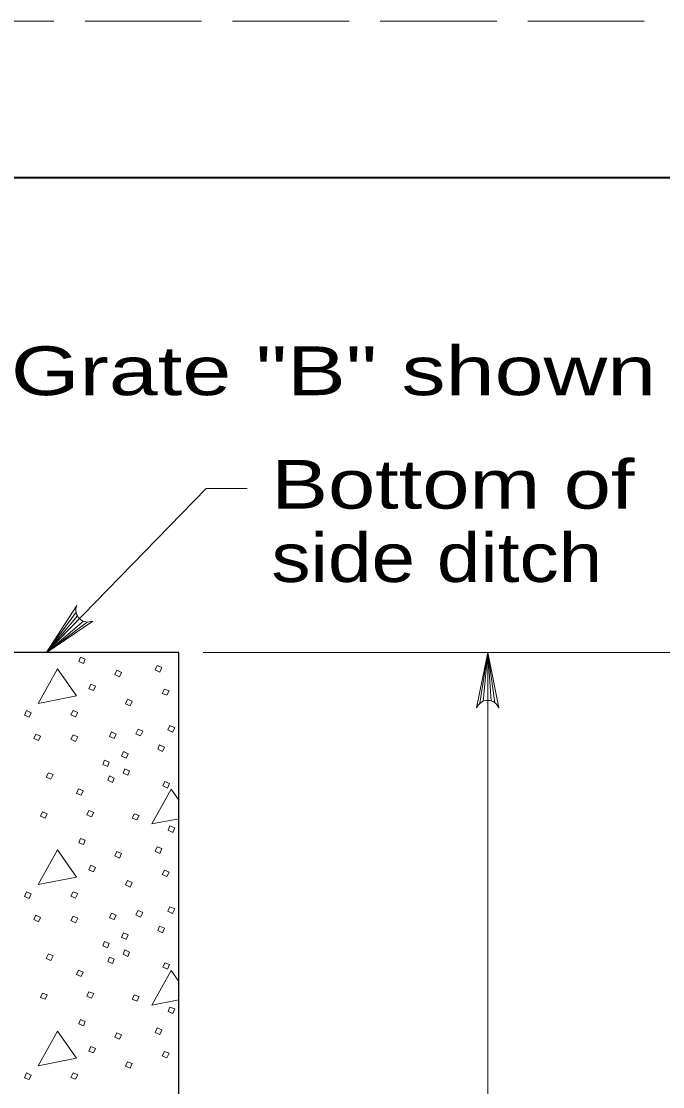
# Model space of a CAD drawing. Extents: x 1036.7 to 1070.7, y 883.9 to 905.9.
# Drawn here: x 1043.194 to 1045.244, y 902.5 to 905.908 of the extents above; entities that cross this region are included whole.
import ezdxf

# ---------------------------------------------------------------- set-up
doc = ezdxf.new("R2010")
doc.units = 0
doc.header["$LTSCALE"] = 0.062
doc.linetypes.add('LONG_DASHED', pattern=[7.5, 6, -1.5])
doc.layers.add('1', color=7, linetype='Continuous', lineweight=13)

msp = doc.modelspace()

# ---------------------------------------------------------------- linework, layer by layer
at = {"layer": '1', "lineweight": 25}
for p, q in [((1038.67333, 905.40825), (1070.17333, 905.40825)), ((1043.69742, 903.88892), (1043.04492, 903.88892)), ((1043.69742, 900.57758), (1043.69742, 903.88892))]:
    msp.add_line(p, q, dxfattribs=at)
at = {"layer": '1'}
for p, q in [((1043.27283, 903.88783), (1043.78483, 904.41408)), ((1043.91542, 904.41408), (1043.78483, 904.41408)), ((1043.36875, 904.01817), (1043.27283, 903.88783)), ((1043.37283, 904.0065), (1043.27283, 903.88783)), ((1043.37983, 903.99742), (1043.27283, 903.88783)), ((1043.39208, 903.98942), (1043.27283, 903.88783)), ((1043.40383, 903.98658), (1043.27283, 903.88783)), ((1043.7755, 903.88892), (1045.66242, 903.88892)), ((1044.65992, 903.72675), (1044.68467, 903.88892)), ((1044.67025, 903.73292), (1044.68467, 903.88892)), ((1044.68467, 900.40125), (1044.68467, 903.88892)), ((1044.68467, 903.73575), (1044.68467, 903.88892)), ((1044.696, 903.73408), (1044.68467, 903.88892)), ((1044.70708, 903.72867), (1044.68467, 903.88892)), ((1043.69742, 903.41675), (1043.673, 903.45158)), ((1043.69742, 902.83708), (1043.673, 902.87192))]:
    msp.add_line(p, q, dxfattribs=at)
at = {"layer": '1', "linetype": 'LONG_DASHED'}
msp.add_lwpolyline([(1036.67333, 883.90825), (1070.67333, 883.90825), (1070.67333, 905.90825), (1036.67333, 905.90825)], close=True, dxfattribs=at)
at = {"layer": '1', "lineweight": 40}
msp.add_lwpolyline([(1038.67333, 905.40825), (1070.17333, 905.40825), (1070.17333, 884.40825), (1038.67333, 884.40825)], close=True, dxfattribs=at)
msp.add_lwpolyline([(1038.67333, 905.40825), (1070.17333, 905.40825), (1070.17333, 884.40825), (1038.67333, 884.40825)], close=True, dxfattribs=at)
at = {"layer": '1'}
for points in [[(1043.42183, 903.98975), (1043.27283, 903.88783), (1043.37117, 904.03925)], [(1044.64925, 903.71192), (1044.68467, 903.88892), (1044.72008, 903.71192)], [(1043.673, 903.45158), (1043.611, 903.34058), (1043.69742, 903.35742)], [(1043.673, 902.87192), (1043.611, 902.76092), (1043.69742, 902.77775)]]:
    msp.add_lwpolyline(points, dxfattribs=at)
for points in [[(1043.38317, 903.87433), (1043.39808, 903.86833), (1043.39217, 903.85433), (1043.37717, 903.86033)], [(1043.30917, 903.83733), (1043.24717, 903.72642), (1043.37017, 903.75042)], [(1043.628, 903.84733), (1043.643, 903.84133), (1043.637, 903.82633), (1043.622, 903.83333)], [(1043.49908, 903.83233), (1043.51408, 903.82533), (1043.50808, 903.81133), (1043.49308, 903.81833)], [(1043.41608, 903.78833), (1043.43108, 903.78133), (1043.42408, 903.76742), (1043.40908, 903.77342)], [(1043.651, 903.77233), (1043.666, 903.76642), (1043.659, 903.75242), (1043.644, 903.75842)], [(1043.53308, 903.73942), (1043.54808, 903.73342), (1043.54208, 903.71842), (1043.52708, 903.72542)], [(1043.21025, 903.70342), (1043.22517, 903.69642), (1043.21917, 903.68242), (1043.20425, 903.68842)], [(1043.35917, 903.70342), (1043.37417, 903.69742), (1043.36717, 903.68342), (1043.35217, 903.68942)], [(1043.48208, 903.63542), (1043.49708, 903.62842), (1043.49108, 903.6145), (1043.47608, 903.6205)], [(1043.56708, 903.64342), (1043.582, 903.63742), (1043.575, 903.6225), (1043.56008, 903.62942)], [(1043.669, 903.65542), (1043.684, 903.64842), (1043.677, 903.63442), (1043.662, 903.64142)], [(1043.24017, 903.62842), (1043.25517, 903.6215), (1043.24917, 903.6075), (1043.23417, 903.6145)], [(1043.35917, 903.6255), (1043.37417, 903.6195), (1043.36717, 903.6045), (1043.35217, 903.6115)], [(1043.52008, 903.5725), (1043.53508, 903.5655), (1043.52908, 903.5515), (1043.51408, 903.5575)], [(1043.636, 903.5935), (1043.651, 903.5865), (1043.645, 903.5725), (1043.63, 903.5795)], [(1043.46008, 903.5445), (1043.47508, 903.5385), (1043.46908, 903.5245), (1043.45408, 903.5305)], [(1043.28017, 903.5045), (1043.29517, 903.4985), (1043.28817, 903.4835), (1043.27317, 903.4905)], [(1043.52508, 903.5175), (1043.54008, 903.5105), (1043.53408, 903.4965), (1043.51908, 903.5035)], [(1043.47608, 903.4945), (1043.49108, 903.4875), (1043.48508, 903.47358), (1043.47008, 903.48058)], [(1043.652, 903.47658), (1043.667, 903.47058), (1043.661, 903.45558), (1043.646, 903.46258)], [(1043.37617, 903.45258), (1043.39117, 903.44658), (1043.38517, 903.43258), (1043.37017, 903.43858)], [(1043.26117, 903.37958), (1043.27617, 903.37358), (1043.27017, 903.35958), (1043.25517, 903.36558)], [(1043.41008, 903.38358), (1043.42508, 903.37758), (1043.41808, 903.36358), (1043.40308, 903.36958)], [(1043.55508, 903.37358), (1043.57008, 903.36758), (1043.56308, 903.35358), (1043.54808, 903.35958)], [(1043.669, 903.33467), (1043.684, 903.32867), (1043.678, 903.31367), (1043.663, 903.32067)], [(1043.38317, 903.29467), (1043.39808, 903.28867), (1043.39217, 903.27467), (1043.37717, 903.28067)], [(1043.30917, 903.25767), (1043.24717, 903.14675), (1043.37017, 903.17075)], [(1043.628, 903.26767), (1043.643, 903.26167), (1043.637, 903.24667), (1043.622, 903.25367)], [(1043.49908, 903.25267), (1043.51408, 903.24567), (1043.50808, 903.23167), (1043.49308, 903.23867)], [(1043.41608, 903.20867), (1043.43108, 903.20167), (1043.42408, 903.18775), (1043.40908, 903.19375)], [(1043.651, 903.19275), (1043.666, 903.18675), (1043.659, 903.17275), (1043.644, 903.17875)], [(1043.53308, 903.15975), (1043.54808, 903.15375), (1043.54208, 903.13875), (1043.52708, 903.14575)], [(1043.21025, 903.12375), (1043.22517, 903.11675), (1043.21917, 903.10275), (1043.20425, 903.10875)], [(1043.35917, 903.12375), (1043.37417, 903.11775), (1043.36717, 903.10375), (1043.35217, 903.10975)], [(1043.48208, 903.05575), (1043.49708, 903.04883), (1043.49108, 903.03483), (1043.47608, 903.04083)], [(1043.56708, 903.06375), (1043.582, 903.05775), (1043.575, 903.04283), (1043.56008, 903.04983)], [(1043.669, 903.07575), (1043.684, 903.06875), (1043.677, 903.05475), (1043.662, 903.06175)], [(1043.24017, 903.04883), (1043.25517, 903.04183), (1043.24917, 903.02783), (1043.23417, 903.03483)], [(1043.35917, 903.04583), (1043.37417, 903.03983), (1043.36717, 903.02483), (1043.35217, 903.03183)], [(1043.52008, 902.99283), (1043.53508, 902.98583), (1043.52908, 902.97183), (1043.51408, 902.97783)], [(1043.636, 903.01383), (1043.651, 903.00683), (1043.645, 902.99283), (1043.63, 902.99983)], [(1043.46008, 902.96483), (1043.47508, 902.95883), (1043.46908, 902.94483), (1043.45408, 902.95083)], [(1043.28017, 902.92483), (1043.29517, 902.91883), (1043.28817, 902.90383), (1043.27317, 902.91083)], [(1043.52508, 902.93783), (1043.54008, 902.93083), (1043.53408, 902.91683), (1043.51908, 902.92383)], [(1043.47608, 902.91483), (1043.49108, 902.90783), (1043.48508, 902.89392), (1043.47008, 902.90092)], [(1043.652, 902.89692), (1043.667, 902.89092), (1043.661, 902.87592), (1043.646, 902.88292)], [(1043.37617, 902.87292), (1043.39117, 902.86692), (1043.38517, 902.85292), (1043.37017, 902.85892)], [(1043.26117, 902.79992), (1043.27617, 902.79392), (1043.27017, 902.77992), (1043.25517, 902.78592)], [(1043.41008, 902.80392), (1043.42508, 902.79792), (1043.41808, 902.78392), (1043.40308, 902.78992)], [(1043.55508, 902.79392), (1043.57008, 902.78792), (1043.56308, 902.77392), (1043.54808, 902.77992)], [(1043.669, 902.755), (1043.684, 902.749), (1043.678, 902.734), (1043.663, 902.741)], [(1043.38317, 902.715), (1043.39808, 902.709), (1043.39217, 902.695), (1043.37717, 902.701)], [(1043.30917, 902.678), (1043.24717, 902.56708), (1043.37017, 902.59108)], [(1043.628, 902.688), (1043.643, 902.682), (1043.637, 902.667), (1043.622, 902.674)], [(1043.49908, 902.673), (1043.51408, 902.666), (1043.50808, 902.652), (1043.49308, 902.659)], [(1043.41608, 902.629), (1043.43108, 902.622), (1043.42408, 902.60808), (1043.40908, 902.61408)], [(1043.651, 902.61308), (1043.666, 902.60708), (1043.659, 902.59308), (1043.644, 902.59908)], [(1043.53308, 902.58008), (1043.54808, 902.57408), (1043.54208, 902.55908), (1043.52708, 902.56608)], [(1043.21025, 902.54408), (1043.22517, 902.53708), (1043.21917, 902.52308), (1043.20425, 902.52908)], [(1043.35917, 902.54408), (1043.37417, 902.53808), (1043.36717, 902.52408), (1043.35217, 902.53008)]]:
    msp.add_lwpolyline(points, close=True, dxfattribs=at)
for centre, start, end in [((1043.40642, 904.02475), 157.78184, 293.60797), ((1044.68472, 903.6976), 22.08782, 157.91395)]:
    msp.add_arc(centre, 0.0382, start, end, dxfattribs=at)

# ---------------------------------------------------------------- texts
for s, width, p in [('Grate "B" shown', 1.35, (1043.16067, 904.71233)), ('Bottom of', 1.3, (1043.99325, 904.34942)), ('side ditch', 1.2, (1043.99325, 904.11475))]:
    msp.add_text(s, height=0.156, dxfattribs=dict(at, width=width)).set_placement(p)

doc.saveas('drawing.dxf')
